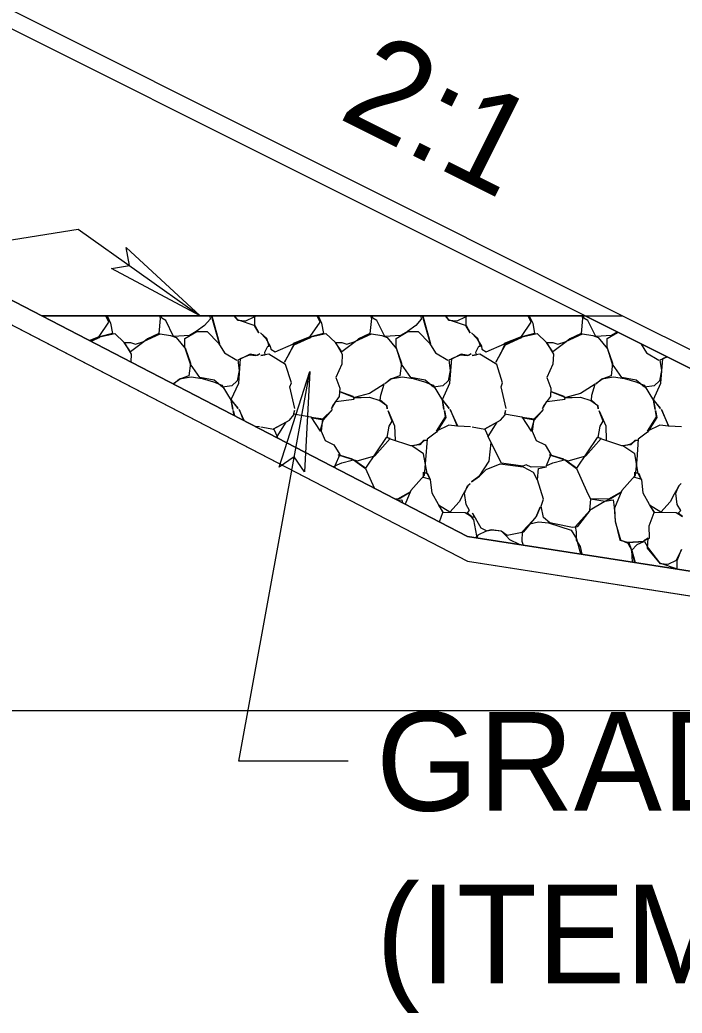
# Model space of a CAD drawing. Extents: x 1574 to 14903, y 7971 to 16537.
# Drawn here: x 14631.02 to 14637.73, y 8496.93 to 8507 of the extents above; entities that cross this region are included whole.
import ezdxf

# ---------------------------------------------------------------- set-up
doc = ezdxf.new("R2010")
doc.units = 0
for name, color, linetype in [('DESIGN - EARTHWORK - Shapes', 7, 'Continuous'), ('DESIGN - SCRATCH - User 1', 7, 'Continuous'), ('DESIGN - SHEET - Light Grid', 7, 'Continuous'), ('DESIGN - TRANSPORTATION - Proposed Layout Patterning', 7, 'Continuous'), ('DESIGN - TYPICAL - Finished Grade and Subgrade', 7, 'Continuous'), ('DESIGN - TYPICAL - Finished Grade Slopes Text', 7, 'Continuous'), ('DESIGN - TYPICAL - Slope Tie Text', 7, 'Continuous'), ('SURVEY - GROUND - Bottom of Topsoil Layer', 7, 'Continuous'), ('SURVEY - GROUND - Top of Ground', 7, 'Continuous')]:
    doc.layers.add(name, color=color, linetype=linetype)

msp = doc.modelspace()

# ---------------------------------------------------------------- linework, layer by layer
at = {"layer": 'DESIGN - EARTHWORK - Shapes'}
for points in [[(14642.161, 8500.61), (14643.012, 8500.617), (14643.012, 8500.867), (14642.161, 8500.86), (14639.329, 8501.174), (14635.553, 8501.765), (14631.238, 8504), (14627.888, 8505.735), (14623.638, 8507.904), (14621.989, 8508.452), (14621.26, 8508.46), (14621.92, 8508.225), (14623.638, 8507.654), (14627.888, 8505.485), (14635.553, 8501.515), (14639.329, 8500.924)], [(14631.238, 8504), (14636.745, 8504), (14627.96, 8508.393), (14621.989, 8508.452), (14623.638, 8507.904), (14627.888, 8505.735)], [(14631.238, 8504), (14636.745, 8504), (14643.012, 8500.867), (14642.161, 8500.86), (14639.329, 8501.174), (14635.553, 8501.765)]]:
    msp.add_lwpolyline(points, close=True, dxfattribs=at)
at = {"layer": 'DESIGN - SCRATCH - User 1'}
msp.add_lwpolyline([(14636.745, 8504), (14631.238, 8504), (14628.574, 8505.38)], dxfattribs=at)
msp.add_lwpolyline([(14643.012, 8500.867), (14636.745, 8504), (14631.238, 8504), (14635.553, 8501.765), (14639.329, 8501.174), (14642.161, 8500.86)], close=True, dxfattribs=at)
at = {"layer": 'DESIGN - SHEET - Light Grid'}
msp.add_line((14600, 8500), (14900, 8500), dxfattribs=at)
at = {"layer": 'DESIGN - TRANSPORTATION - Proposed Layout Patterning'}
for p, q in [((14631.238, 8504), (14637.124, 8504)), ((14631.256, 8504), (14631.252, 8503.993)), ((14631.26, 8503.989), (14631.265, 8504)), ((14633.444, 8502.876), (14633.406, 8502.877))]:
    msp.add_line(p, q, dxfattribs=at)
for points in [[(14631.72, 8503.75), (14631.819, 8503.791), (14631.919, 8503.936), (14631.888, 8504)], [(14631.9, 8504), (14631.934, 8503.926), (14631.954, 8503.821), (14631.824, 8503.786), (14631.979, 8503.821), (14632.074, 8503.731), (14632.144, 8503.611), (14632.14, 8503.533)], [(14632.431, 8504), (14632.439, 8503.971), (14632.424, 8503.821), (14632.309, 8503.766), (14632.274, 8503.736), (14632.139, 8503.636), (14632.074, 8503.731), (14632.139, 8503.731), (14632.189, 8503.711), (14632.264, 8503.736), (14632.439, 8503.816), (14632.544, 8503.801), (14632.599, 8503.781), (14632.694, 8503.666), (14632.744, 8503.521), (14632.729, 8503.391), (14632.644, 8503.361), (14632.574, 8503.311), (14632.634, 8503.361), (14632.754, 8503.381), (14632.864, 8503.366), (14632.979, 8503.331), (14633.064, 8503.296), (14633.159, 8503.141), (14633.174, 8503.051), (14633.159, 8503.146), (14633.229, 8503.061), (14633.159, 8503.151), (14633.234, 8503.316), (14633.254, 8503.566), (14633.344, 8503.606), (14633.409, 8503.596), (14633.449, 8503.616), (14633.424, 8503.596), (14633.349, 8503.611), (14633.264, 8503.566), (14633.224, 8503.551), (14633.239, 8503.446), (14633.219, 8503.341), (14633.164, 8503.291), (14633.069, 8503.276), (14632.984, 8503.346), (14632.839, 8503.376), (14632.744, 8503.511), (14632.689, 8503.681), (14632.689, 8503.771), (14632.809, 8503.841), (14632.914, 8503.841), (14633.029, 8503.721), (14633.089, 8503.626), (14633.214, 8503.551)], [(14632.941, 8504), (14632.944, 8503.966), (14632.889, 8503.901), (14632.804, 8503.841), (14632.734, 8503.801), (14632.574, 8503.791), (14632.494, 8503.951), (14632.454, 8503.976), (14632.448, 8504)], [(14632.962, 8504), (14633.039, 8503.716), (14632.958, 8504)], [(14633.189, 8504), (14633.219, 8503.961), (14633.399, 8503.901), (14633.439, 8503.826), (14633.399, 8503.896), (14633.399, 8503.986), (14633.405, 8504)], [(14633.396, 8504), (14633.389, 8503.986), (14633.304, 8503.946), (14633.229, 8503.951), (14633.189, 8504)], [(14633.804, 8503.061), (14633.754, 8503.281), (14633.769, 8503.321), (14633.709, 8503.506), (14633.539, 8503.611), (14633.459, 8503.596), (14633.504, 8503.606), (14633.499, 8503.631), (14633.529, 8503.691), (14633.544, 8503.691), (14633.519, 8503.771), (14633.454, 8503.826), (14633.509, 8503.771), (14633.554, 8503.691), (14633.559, 8503.661), (14633.604, 8503.636), (14633.789, 8503.716), (14633.964, 8503.781), (14633.794, 8503.701), (14633.754, 8503.631), (14633.699, 8503.531), (14633.754, 8503.626), (14633.789, 8503.701), (14633.789, 8503.721), (14633.959, 8503.791), (14634.059, 8503.936), (14634.028, 8504)], [(14634.04, 8504), (14634.074, 8503.926), (14634.094, 8503.821), (14633.964, 8503.786), (14634.119, 8503.821), (14634.214, 8503.731), (14634.284, 8503.611), (14634.279, 8503.511), (14634.219, 8503.376), (14634.259, 8503.266), (14634.254, 8503.181), (14634.184, 8503.086), (14634.174, 8503.056), (14634.219, 8503.131), (14634.404, 8503.156), (14634.394, 8503.181), (14634.264, 8503.231), (14634.409, 8503.171), (14634.474, 8503.171), (14634.559, 8503.176), (14634.664, 8503.141), (14634.734, 8503.091), (14634.739, 8503.056), (14634.734, 8503.086), (14634.669, 8503.146), (14634.674, 8503.196), (14634.709, 8503.306), (14634.559, 8503.211), (14634.409, 8503.171)], [(14634.571, 8504), (14634.579, 8503.971), (14634.564, 8503.821), (14634.449, 8503.766), (14634.414, 8503.736), (14634.279, 8503.636), (14634.214, 8503.731), (14634.279, 8503.731), (14634.329, 8503.711), (14634.404, 8503.736), (14634.579, 8503.816), (14634.684, 8503.801), (14634.739, 8503.781), (14634.834, 8503.666), (14634.884, 8503.521), (14634.869, 8503.391), (14634.784, 8503.361), (14634.714, 8503.311), (14634.774, 8503.361), (14634.894, 8503.381), (14635.004, 8503.366), (14635.119, 8503.331), (14635.204, 8503.296), (14635.299, 8503.141), (14635.314, 8503.051), (14635.299, 8503.146), (14635.369, 8503.061), (14635.299, 8503.151), (14635.374, 8503.316), (14635.394, 8503.566), (14635.484, 8503.606), (14635.549, 8503.596), (14635.589, 8503.616), (14635.564, 8503.596), (14635.489, 8503.611), (14635.404, 8503.566), (14635.364, 8503.551), (14635.379, 8503.446), (14635.359, 8503.341), (14635.304, 8503.291), (14635.209, 8503.276), (14635.124, 8503.346), (14634.979, 8503.376), (14634.884, 8503.511), (14634.829, 8503.681), (14634.829, 8503.771), (14634.949, 8503.841), (14635.054, 8503.841), (14635.169, 8503.721), (14635.229, 8503.626), (14635.354, 8503.551)], [(14635.081, 8504), (14635.084, 8503.966), (14635.029, 8503.901), (14634.944, 8503.841), (14634.874, 8503.801), (14634.714, 8503.791), (14634.634, 8503.951), (14634.594, 8503.976), (14634.588, 8504)], [(14635.102, 8504), (14635.179, 8503.716), (14635.098, 8504)], [(14635.329, 8504), (14635.359, 8503.961), (14635.539, 8503.901), (14635.579, 8503.826), (14635.539, 8503.896), (14635.539, 8503.986), (14635.545, 8504)], [(14635.536, 8504), (14635.529, 8503.986), (14635.444, 8503.946), (14635.369, 8503.951), (14635.329, 8504)], [(14635.944, 8503.061), (14635.894, 8503.281), (14635.909, 8503.321), (14635.849, 8503.506), (14635.679, 8503.611), (14635.599, 8503.596), (14635.644, 8503.606), (14635.639, 8503.631), (14635.669, 8503.691), (14635.684, 8503.691), (14635.659, 8503.771), (14635.594, 8503.826), (14635.649, 8503.771), (14635.694, 8503.691), (14635.699, 8503.661), (14635.744, 8503.636), (14635.929, 8503.716), (14636.104, 8503.781), (14635.934, 8503.701), (14635.894, 8503.631), (14635.839, 8503.531), (14635.894, 8503.626), (14635.929, 8503.701), (14635.929, 8503.721), (14636.099, 8503.791), (14636.199, 8503.936), (14636.168, 8504)], [(14636.18, 8504), (14636.214, 8503.926), (14636.234, 8503.821), (14636.104, 8503.786), (14636.259, 8503.821), (14636.354, 8503.731), (14636.424, 8503.611), (14636.419, 8503.511), (14636.359, 8503.376), (14636.399, 8503.266), (14636.394, 8503.181), (14636.324, 8503.086), (14636.314, 8503.056), (14636.359, 8503.131), (14636.544, 8503.156), (14636.534, 8503.181), (14636.404, 8503.231), (14636.549, 8503.171), (14636.614, 8503.171), (14636.699, 8503.176), (14636.804, 8503.141), (14636.874, 8503.091), (14636.879, 8503.056), (14636.874, 8503.086), (14636.809, 8503.146), (14636.814, 8503.196), (14636.849, 8503.306), (14636.699, 8503.211), (14636.549, 8503.171)], [(14636.711, 8504), (14636.719, 8503.971), (14636.704, 8503.821), (14636.589, 8503.766), (14636.554, 8503.736), (14636.419, 8503.636), (14636.354, 8503.731), (14636.419, 8503.731), (14636.469, 8503.711), (14636.544, 8503.736), (14636.719, 8503.816), (14636.824, 8503.801), (14636.879, 8503.781), (14636.974, 8503.666), (14637.024, 8503.521), (14637.009, 8503.391), (14636.924, 8503.361), (14636.854, 8503.311), (14636.914, 8503.361), (14637.034, 8503.381), (14637.144, 8503.366), (14637.259, 8503.331), (14637.344, 8503.296), (14637.439, 8503.141), (14637.454, 8503.051), (14637.439, 8503.146), (14637.509, 8503.061), (14637.439, 8503.151), (14637.514, 8503.316), (14637.534, 8503.566), (14637.571, 8503.583)], [(14637.07, 8503.833), (14637.014, 8503.801), (14636.854, 8503.791), (14636.774, 8503.951), (14636.734, 8503.976), (14636.728, 8504)], [(14631.729, 8503.746), (14631.824, 8503.781), (14631.739, 8503.741)], [(14637.574, 8503.582), (14637.544, 8503.566), (14637.504, 8503.551), (14637.519, 8503.446), (14637.499, 8503.341), (14637.444, 8503.291), (14637.349, 8503.276), (14637.264, 8503.346), (14637.119, 8503.376), (14637.024, 8503.511), (14636.969, 8503.681), (14636.969, 8503.771), (14637.073, 8503.832)], [(14637.315, 8503.711), (14637.369, 8503.626), (14637.494, 8503.551)], [(14633.187, 8502.991), (14633.179, 8503.041), (14633.19, 8502.989)], [(14633.289, 8502.938), (14633.239, 8503.051), (14633.284, 8502.94)], [(14633.459, 8502.876), (14633.589, 8502.851), (14633.624, 8502.776), (14633.714, 8502.921), (14633.584, 8502.851), (14633.749, 8502.941), (14633.794, 8502.996), (14633.799, 8503.041), (14633.789, 8503.006), (14633.964, 8502.976), (14634.059, 8502.831), (14634.094, 8502.951), (14633.964, 8502.971), (14634.094, 8502.946), (14634.184, 8503.051), (14634.084, 8502.951), (14634.069, 8502.831), (14634.109, 8502.736), (14634.199, 8502.691), (14634.259, 8502.596), (14634.209, 8502.481), (14634.279, 8502.511), (14634.384, 8502.536), (14634.389, 8502.546), (14634.244, 8502.591), (14634.434, 8502.531), (14634.614, 8502.581), (14634.769, 8502.756), (14634.729, 8502.766), (14634.519, 8502.456), (14634.399, 8502.541), (14634.519, 8502.451), (14634.606, 8502.256)], [(14635.269, 8501.912), (14635.304, 8502.006), (14635.394, 8502.011), (14635.529, 8502.006), (14635.594, 8501.966), (14635.549, 8502.001), (14635.574, 8502.026), (14635.539, 8502.086), (14635.524, 8502.201), (14635.554, 8502.276), (14635.579, 8502.301), (14635.559, 8502.281), (14635.509, 8502.191), (14635.469, 8502.116), (14635.374, 8502.011), (14635.259, 8502.081), (14635.304, 8502.011), (14635.259, 8502.086), (14635.194, 8502.201), (14635.179, 8502.341), (14635.109, 8502.361), (14635.109, 8502.416), (14635.149, 8502.401), (14635.174, 8502.341), (14635.144, 8502.401), (14635.109, 8502.601), (14634.989, 8502.681), (14635.069, 8502.701), (14635.119, 8502.741), (14635.144, 8502.736), (14635.109, 8502.736), (14635.069, 8502.691), (14634.979, 8502.681), (14634.774, 8502.751), (14634.739, 8502.766), (14634.759, 8502.881), (14634.789, 8502.931), (14634.749, 8503.036), (14634.814, 8502.886), (14634.819, 8502.741)], [(14635.584, 8502.876), (14635.454, 8502.881), (14635.379, 8503.051), (14635.449, 8502.881), (14635.364, 8502.891), (14635.239, 8502.831), (14635.329, 8502.976), (14635.319, 8503.041), (14635.334, 8502.971), (14635.239, 8502.821), (14635.144, 8502.751), (14635.129, 8502.541), (14635.114, 8502.381), (14634.979, 8502.231), (14634.921, 8502.092)], [(14635.599, 8502.876), (14635.729, 8502.851), (14635.764, 8502.776), (14635.854, 8502.921), (14635.724, 8502.851), (14635.889, 8502.941), (14635.934, 8502.996), (14635.939, 8503.041), (14635.929, 8503.006), (14636.104, 8502.976), (14636.199, 8502.831), (14636.234, 8502.951), (14636.104, 8502.971), (14636.234, 8502.946), (14636.324, 8503.051), (14636.224, 8502.951), (14636.209, 8502.831), (14636.249, 8502.736), (14636.339, 8502.691), (14636.399, 8502.596), (14636.349, 8502.481), (14636.419, 8502.511), (14636.524, 8502.536), (14636.529, 8502.546), (14636.384, 8502.591), (14636.574, 8502.531), (14636.754, 8502.581), (14636.909, 8502.756), (14636.869, 8502.766), (14636.659, 8502.456), (14636.539, 8502.541), (14636.659, 8502.451), (14636.759, 8502.226), (14636.799, 8502.141), (14636.789, 8502.031), (14636.944, 8502.121), (14636.999, 8502.146), (14637.114, 8502.216), (14636.984, 8502.141), (14636.799, 8502.146), (14636.949, 8502.121), (14637.029, 8502.136), (14637.039, 8502.061), (14637.049, 8501.921), (14637.099, 8501.726), (14637.189, 8501.701), (14637.214, 8501.626), (14637.224, 8501.504)], [(14637.679, 8501.432), (14637.679, 8501.521), (14637.724, 8501.631), (14637.669, 8501.521), (14637.584, 8501.481), (14637.509, 8501.486), (14637.379, 8501.646), (14637.384, 8501.746), (14637.339, 8501.721), (14637.399, 8501.746), (14637.394, 8501.871), (14637.444, 8502.006), (14637.534, 8502.011), (14637.669, 8502.006), (14637.734, 8501.966), (14637.689, 8502.001), (14637.714, 8502.026), (14637.679, 8502.086), (14637.664, 8502.201), (14637.694, 8502.276), (14637.719, 8502.301), (14637.699, 8502.281), (14637.649, 8502.191), (14637.609, 8502.116), (14637.514, 8502.011), (14637.399, 8502.081), (14637.444, 8502.011), (14637.399, 8502.086), (14637.334, 8502.201), (14637.319, 8502.341), (14637.249, 8502.361), (14637.249, 8502.416), (14637.289, 8502.401), (14637.314, 8502.341), (14637.284, 8502.401), (14637.249, 8502.601), (14637.129, 8502.681), (14637.209, 8502.701), (14637.259, 8502.741), (14637.284, 8502.736), (14637.249, 8502.736), (14637.209, 8502.691), (14637.119, 8502.681), (14636.914, 8502.751), (14636.879, 8502.766), (14636.899, 8502.881), (14636.929, 8502.931), (14636.889, 8503.036), (14636.954, 8502.886), (14636.959, 8502.741)], [(14637.724, 8502.876), (14637.594, 8502.881), (14637.519, 8503.051), (14637.589, 8502.881), (14637.504, 8502.891), (14637.379, 8502.831), (14637.469, 8502.976), (14637.459, 8503.041), (14637.474, 8502.971), (14637.379, 8502.821), (14637.284, 8502.751), (14637.269, 8502.541), (14637.254, 8502.381), (14637.119, 8502.231), (14637.044, 8502.051), (14637.049, 8501.916), (14637.104, 8501.731), (14637.179, 8501.696), (14637.219, 8501.621), (14637.252, 8501.499)], [(14633.628, 8502.762), (14633.619, 8502.781), (14633.627, 8502.762)], [(14636.717, 8501.583), (14636.699, 8501.661), (14636.659, 8501.726), (14636.659, 8501.811), (14636.649, 8501.866), (14636.794, 8502.026), (14636.664, 8501.861), (14636.619, 8501.856), (14636.434, 8501.891), (14636.389, 8501.901), (14636.324, 8501.956), (14636.299, 8502.071), (14636.324, 8502.141), (14636.264, 8502.336), (14636.274, 8502.451), (14636.354, 8502.471), (14636.199, 8502.466), (14636.149, 8502.491), (14636.114, 8502.476), (14635.899, 8502.506), (14635.789, 8502.721), (14635.759, 8502.781), (14635.789, 8502.716), (14635.769, 8502.526), (14635.669, 8502.371), (14635.594, 8502.316), (14635.674, 8502.376), (14635.744, 8502.441), (14635.884, 8502.501), (14636.119, 8502.471), (14636.219, 8502.416), (14636.259, 8502.336)], [(14634.198, 8502.467), (14634.214, 8502.471), (14634.192, 8502.47)], [(14634.837, 8502.136), (14634.859, 8502.146), (14634.974, 8502.216), (14634.844, 8502.141), (14634.827, 8502.141)], [(14634.851, 8502.129), (14634.889, 8502.136), (14634.893, 8502.107)], [(14635.642, 8501.751), (14635.649, 8501.771), (14635.619, 8501.931), (14635.594, 8501.961), (14635.624, 8501.961), (14635.604, 8502.001), (14635.689, 8501.851), (14635.749, 8501.821), (14635.799, 8501.831), (14635.894, 8501.821), (14635.954, 8501.776), (14636.124, 8501.811), (14636.249, 8501.961), (14636.289, 8502.061), (14636.249, 8501.961), (14636.169, 8501.876), (14636.109, 8501.811), (14636.104, 8501.716), (14636.117, 8501.677)], [(14636.184, 8501.891), (14636.274, 8501.911), (14636.374, 8501.901), (14636.604, 8501.826), (14636.659, 8501.741), (14636.698, 8501.586)], [(14636.081, 8501.682), (14635.984, 8501.731), (14635.944, 8501.771), (14635.899, 8501.816), (14635.794, 8501.831), (14635.744, 8501.816), (14635.659, 8501.776), (14635.648, 8501.75)], [(14637.248, 8501.5), (14637.214, 8501.621), (14637.274, 8501.681), (14637.339, 8501.711), (14637.174, 8501.701), (14637.349, 8501.711), (14637.389, 8501.641), (14637.499, 8501.496), (14637.679, 8501.436), (14637.681, 8501.432)]]:
    msp.add_lwpolyline(points, dxfattribs=at)
at = {"layer": 'DESIGN - TYPICAL - Finished Grade and Subgrade'}
for p, q in [((14628.347, 8508.388), (14637.124, 8504)), ((14631.238, 8504), (14637.124, 8504)), ((14637.124, 8504), (14643.384, 8500.87))]:
    msp.add_line(p, q, dxfattribs=at)
at = {"layer": 'DESIGN - TYPICAL - Slope Tie Text'}
for points in [[(14625.684, 8503.931), (14631.608, 8504.878), (14632.843, 8504)], [(14632.843, 8504), (14631.944, 8504.48), (14632.126, 8504.51), (14632.095, 8504.692), (14632.843, 8504)], [(14634.344, 8499.485), (14633.234, 8499.485), (14633.954, 8503.437)], [(14633.954, 8503.437), (14633.9, 8502.42), (14633.796, 8502.572), (14633.645, 8502.467), (14633.954, 8503.437)]]:
    msp.add_lwpolyline(points, dxfattribs=at)
for points in [[(14632.843, 8504), (14631.944, 8504.48), (14632.126, 8504.51), (14632.095, 8504.692)], [(14633.954, 8503.437), (14633.9, 8502.42), (14633.796, 8502.572), (14633.645, 8502.467)]]:
    msp.add_lwpolyline(points, close=True, dxfattribs=at)
at = {"layer": 'SURVEY - GROUND - Bottom of Topsoil Layer'}
for p, q in [((14627.888, 8505.485), (14635.553, 8501.515)), ((14635.553, 8501.515), (14639.329, 8500.924))]:
    msp.add_line(p, q, dxfattribs=at)
at = {"layer": 'SURVEY - GROUND - Top of Ground'}
msp.add_lwpolyline([(14616.951, 8510.241), (14621.92, 8508.475), (14623.638, 8507.904), (14627.888, 8505.735), (14635.553, 8501.765), (14639.329, 8501.174), (14642.161, 8500.86), (14651.084, 8500.933), (14652.282, 8500.879), (14653.214, 8500.973), (14654.895, 8501.691), (14662.41, 8505.243)], dxfattribs=at)

# ---------------------------------------------------------------- texts
at = {"layer": 'DESIGN - TYPICAL - Finished Grade Slopes Text'}
msp.add_text('2:1', height=1, rotation=333.4349, dxfattribs=at).set_placement((14634.227, 8506.009))
at = {"layer": 'DESIGN - TYPICAL - Slope Tie Text'}
for s, p in [('GRADED SOLID ROCK', (14634.626, 8498.984)), ('(ITEM NO. 203-02.01)', (14634.626, 8497.234))]:
    msp.add_text(s, height=1, rotation=360, dxfattribs=at).set_placement(p)

doc.saveas('drawing.dxf')
